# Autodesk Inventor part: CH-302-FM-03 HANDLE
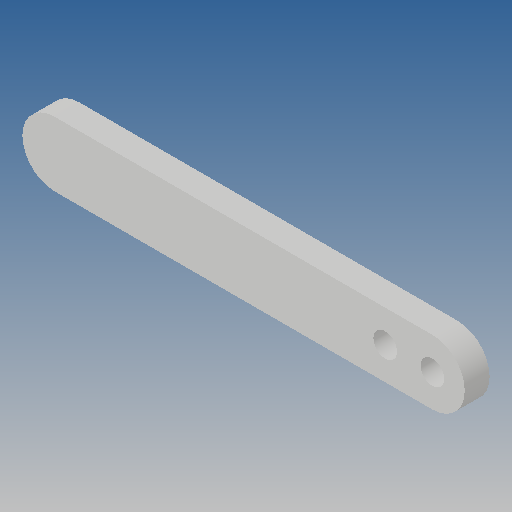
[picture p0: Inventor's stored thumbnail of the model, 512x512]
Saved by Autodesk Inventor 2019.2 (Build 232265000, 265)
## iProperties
Created: 2013-03
Part Number: CH-302-FM-03 HANDLE
Material: Ogólny
Document SubType Name: Modeling
Designer: CADENGINEERING4
Density: 1 g/cm^3
Appearance: Domyślna
Author: CADENGINEERING4
Revision Number: ÈÎºÎ
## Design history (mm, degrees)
feature "À­Éì1"
node "Bryła1"
